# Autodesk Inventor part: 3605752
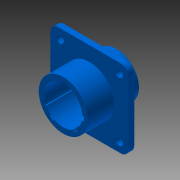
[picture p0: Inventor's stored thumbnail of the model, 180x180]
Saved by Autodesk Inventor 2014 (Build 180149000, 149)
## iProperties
Company: Autodesk
GlobalPropertyList: <PropertyList/>
Shininess: 64.0
Length Units: 11272
Angle Units: 11279
Time Units: 11290
Mass Units: 11286
Length Display Precision: 3
Angle Display Precision: 2
Compacted: True
Part Number: 3605752
Document SubType Name: Modeling
Created: 2003-10
Designer: Garin Gardiner
Manufacturer: Standard
Standards Organization: Custom
Project: AIP
Description: AMP
Density: 1 g/cm^3
Mass: 5.43422 g
Surface Area: 51.8347 cm^2
Volume: 5.43422 cm^3
Material: Generic
Appearance: Blue (Flat)
Density: 0.0
Volumn: 0.0
Area: 0.0
PropertySet Name: Model Information
Control State: 0
Master: False
Checked Out: False
Subject: AMP
Author: Garin Gardiner
Revision Number: 0
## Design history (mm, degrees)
sketch "Sketch1"
  geometry: L1 (16.281, 16.281)-(-16.281, 16.281); L2 (-16.281, 16.281)-(-16.281, -16.281); L3 (-16.281, -16.281)-(16.281, -16.281); L4 (16.281, -16.281)-(16.281, 16.281); 3 further points
  constraints: 8 end point, 2 midpoint, 2 parallel, 2 perpendicular, 1 horizontal, 1 horizontal alignment, 1 vertical alignment
  dimensions: "d0" = 32.5628 distance of L1.start L1.end
extrude "Extrusion1" new body sketch "Sketch1" distance "d1" = 2.3876; taper "d2" = 0 deg
fillet "Fillet1" dims "d3" = 3.175
sketch "Sketch2"
  geometry: L1 (13.106, -16.281)-(-13.106, -16.281) reference; L2 (16.281, 13.106)-(16.281, -13.106) reference; L3 (-13.106, 16.281)-(13.106, 16.281) reference; L4 (-16.281, -13.106)-(-16.281, 13.106) reference; 4 further points
  constraints: 2 horizontal alignment, 2 vertical alignment
  dimensions: "d4" = 3.9624 distance from line of L4 point (-12.319, 12.319); "d5" = 3.9624 distance from line of L3 point (-12.319, 12.319) (= d4); "d6" = 3.9624 distance from line of L1 point (-12.319, -12.319) (= d4); "d7" = 3.9624 distance from line of L2 point (12.319, -12.319) (= d4)
hole "Hole1" sketch "Sketch2" at (-12.319, 12.319), (12.319, 12.319), (12.319, -12.319), (-12.319, -12.319) diameter "d8" = 3.1496; stored, may be unused: countersink angle "d12" = 82 deg, drill point angle "d14" = 118 deg; dims "d9" = 12.7, "d10" = 9.525, "d11" = 6.35, "d13" = 19.05
sketch "Sketch3"
  geometry: L1 (16.281, 13.106)-(16.281, -13.106) reference; L2 (-13.106, 16.281)-(13.106, 16.281) reference; C1 r 10.262 at (0, 0); 2 further points
  constraints: 2 midpoint, 1 centre point, 1 horizontal alignment, 1 vertical alignment
  dimensions: "d15" = 20.5232 diameter of C1
extrude "Extrusion2" join sketch "Sketch3" distance "d16" = 10.922; taper "d17" = 0 deg
sketch "Sketch4"
  geometry: C1 r 10.262 at (0, 0) reference; C2 r 7.938 at (0, 0)
  constraints: 1 centre point, 1 coincident
  dimensions: "d19" = 7.9375 radius of C2
extrude "Extrusion3" cut sketch "Sketch4" distance "d20" = 11.684; taper "d21" = 0 deg
sketch "Sketch5"
  geometry: L1 (-1.651, 7.764)-(-1.651, 8.528); L2 (1.651, 7.764)-(1.651, 8.528); C1 r 10.262 at (0, 0) reference; A1 r 7.937 centre (0, 0) between (-1.651, 7.764) and (1.651, 7.764) reference; A2 r 8.687 centre (0, 0) between (-1.651, 8.528) and (1.651, 8.528)
  constraints: 4 end point, 4 point on circle, 2 parallel, 1 centre point, 1 coincident, 1 vertical
  dimensions: "d22" = 8.6868 radius of A2; "d23" = 3.302 distance between parallel lines of L2 L1
extrude "Extrusion4" cut sketch "Sketch5" stored distance "d24" = 8.89; taper "d25" = 0 deg
sketch "Sketch6"
  geometry: L1 (1.651, 8.528)-(1.651, 7.764) reference; L2 (-1.651, 7.764)-(-1.651, 8.528) reference; L3 (-7.731, -1.8)-(-8.439, -2.058); L4 (-7.079, -3.59)-(-7.788, -3.848); L5 (-5.3, -5.909)-(-5.733, -6.527); L6 (-4.172, -7.619)-(-3.74, -7.001); L7 (3.74, -7.001)-(4.172, -7.619); L8 (5.3, -5.909)-(5.733, -6.527); L9 (7.933, 0.262)-(8.685, 0.196); L10 (7.767, -1.636)-(8.519, -1.701); C1 r 10.262 at (0, 0) reference; A1 r 8.687 centre (0, 0) between (1.651, 8.528) and (-1.651, 8.528) reference; 2 further points
  constraints: 16 end point, 8 parallel, 1 coincident, 21 other
  dimensions: "d26" = 110 deg angle of L2 L3; "d27" = 1.905 distance between parallel lines of L4 L3; "d30" = 1.905 distance between parallel lines of L6 L5 (= d27); "d31" = 35 deg angle of L4 L5; "d32" = 70 deg angle of L7 L6; "d33" = 1.905 distance between parallel lines of L8 L7 (= d30); "d34" = 1.905 distance between parallel lines of L9 L10 (= d33); "d35" = 50 deg angle of L10 L8
extrude "Extrusion5" cut sketch "Sketch6" stored distance "d28" = 8.89; taper "d29" = 0 deg
sketch "Sketch8"
  geometry: L1 (-13.106, 16.281)-(13.106, 16.281) reference; L2 (-16.281, -13.106)-(-16.281, 13.106) reference; C1 r 10.732 at (0, 0); 2 further points
  constraints: 2 midpoint, 1 centre point, 1 horizontal alignment, 1 vertical alignment
  dimensions: "d39" = 21.463 diameter of C1
extrude "Extrusion7" join sketch "Sketch8" distance "d40" = 1.82925; taper "d41" = 0 deg
sketch "Sketch27"
  geometry: C1 r 10.732 at (0, 0) reference; C2 r 9.335 at (0, 0)
  constraints: 1 centre point, 1 coincident
  dimensions: "d82" = 18.669 diameter of C2
extrude "Extrusion11" join sketch "Sketch27" distance "d83" = 7.112; taper "d84" = 0 deg
sketch "Sketch28"
  geometry: C1 r 9.335 at (0, 0) reference; C2 r 10.262 at (0, 0) reference; 1 further point
  dimensions: "d85" = 3.9624 horizontal distance of C2.centre point (-3.962, -3.962); "d86" = 3.9624 horizontal distance of C1.centre point (-3.962, -3.962)
hole "Hole4" sketch "Sketch28" at (-3.962, -3.962) diameter "d87" = 3.302; stored, may be unused: countersink angle "d91" = 82 deg, drill point angle "d93" = 118 deg; dims "d88" = 12.7, "d89" = 9.525, "d90" = 6.35, "d92" = 19.05
pattern_linear "Rectangular Pattern1" dims "d96" = 3.9624, "d99" = 3.9624
sketch "Sketch29"
  geometry: L1 (-10.439, 2.487)-(-10.439, -2.487); L2 (-16.281, -13.106)-(-16.281, 13.106) reference; A1 r 10.732 centre (0, 0) between (-10.439, 2.487) and (-10.439, -2.487) reference
  constraints: 2 end point, 2 point on circle, 1 vertical
  dimensions: "d100" = 5.842 distance between parallel lines of L2 L1
extrude "Extrusion12" cut sketch "Sketch29" stored distance "d101" = 7.112; taper "d102" = 0 deg
sketch "Sketch30"
  geometry: L1 (-7.548, 4.646)-(-6.384, 4.646); L2 (-6.384, 4.646)-(-6.384, 3.117); L3 (-6.384, 3.117)-(-7.548, 3.117); L4 (-7.548, 3.117)-(-7.548, 4.646); L5 (-7.518, -0.805)-(-7.518, 0.724); L6 (-7.518, 0.724)-(-6.354, 0.724); L7 (-6.354, 0.724)-(-6.354, -0.805); L8 (-6.354, -0.805)-(-7.518, -0.805); L9 (-7.367, -4.967)-(-7.367, -3.437); L10 (-7.367, -3.437)-(-6.204, -3.437); L11 (-6.204, -3.437)-(-6.204, -4.967); L12 (-6.204, -4.967)-(-7.367, -4.967); L13 (6.018, 3.208)-(6.018, 4.738); L14 (6.018, 4.738)-(7.181, 4.738); L15 (7.181, 4.738)-(7.181, 3.208); L16 (7.181, 3.208)-(6.018, 3.208); L17 (6.136, -0.727)-(6.136, 0.803); L18 (6.136, 0.803)-(7.3, 0.803); L19 (7.3, 0.803)-(7.3, -0.727); L20 (7.3, -0.727)-(6.136, -0.727); L21 (6.258, -4.875)-(6.258, -3.346); L22 (6.258, -3.346)-(7.422, -3.346); L23 (7.422, -3.346)-(7.422, -4.875); L24 (7.422, -4.875)-(6.258, -4.875)
  constraints: 12 other
emboss "Emboss5" sketch "Sketch30" dims "d8" = 3.1496, "d10" = 9.525, "d11" = 6.35, "d13" = 19.05, "d103" = 0.0254, "d104" = 0
sketch "Sketch32"
  geometry: L1 (-6.886, 3.995)-(-5.722, 3.995); L2 (-5.722, 3.995)-(-5.722, 2.465); L3 (-5.722, 2.465)-(-6.886, 2.465); L4 (-6.886, 2.465)-(-6.886, 3.995); L5 (5.86, -0.839)-(5.86, 0.69); L6 (5.86, 0.69)-(7.024, 0.69); L7 (7.024, 0.69)-(7.024, -0.839); L8 (7.024, -0.839)-(5.86, -0.839); L9 (5.84, -3.84)-(5.84, -2.311); L10 (5.84, -2.311)-(7.004, -2.311); L11 (7.004, -2.311)-(7.004, -3.84); L12 (7.004, -3.84)-(5.84, -3.84); L13 (5.881, 2.253)-(5.881, 3.782); L14 (5.881, 3.782)-(7.045, 3.782); L15 (7.045, 3.782)-(7.045, 2.253); L16 (7.045, 2.253)-(5.881, 2.253); L17 (-6.969, -0.761)-(-6.969, 0.769); L18 (-6.969, 0.769)-(-5.805, 0.769); L19 (-5.805, 0.769)-(-5.805, -0.761); L20 (-5.805, -0.761)-(-6.969, -0.761); L21 (-6.949, -3.851)-(-6.949, -2.356); L22 (-6.949, -2.356)-(-5.785, -2.356); L23 (-5.785, -2.356)-(-5.785, -3.851); L24 (-5.785, -3.851)-(-6.949, -3.851)
  constraints: 12 other
emboss "Emboss6" sketch "Sketch32" dims "d8" = 3.1496, "d10" = 9.525, "d11" = 6.35, "d13" = 19.05, "d105" = 0.0254, "d106" = 0
body "Solid1"
